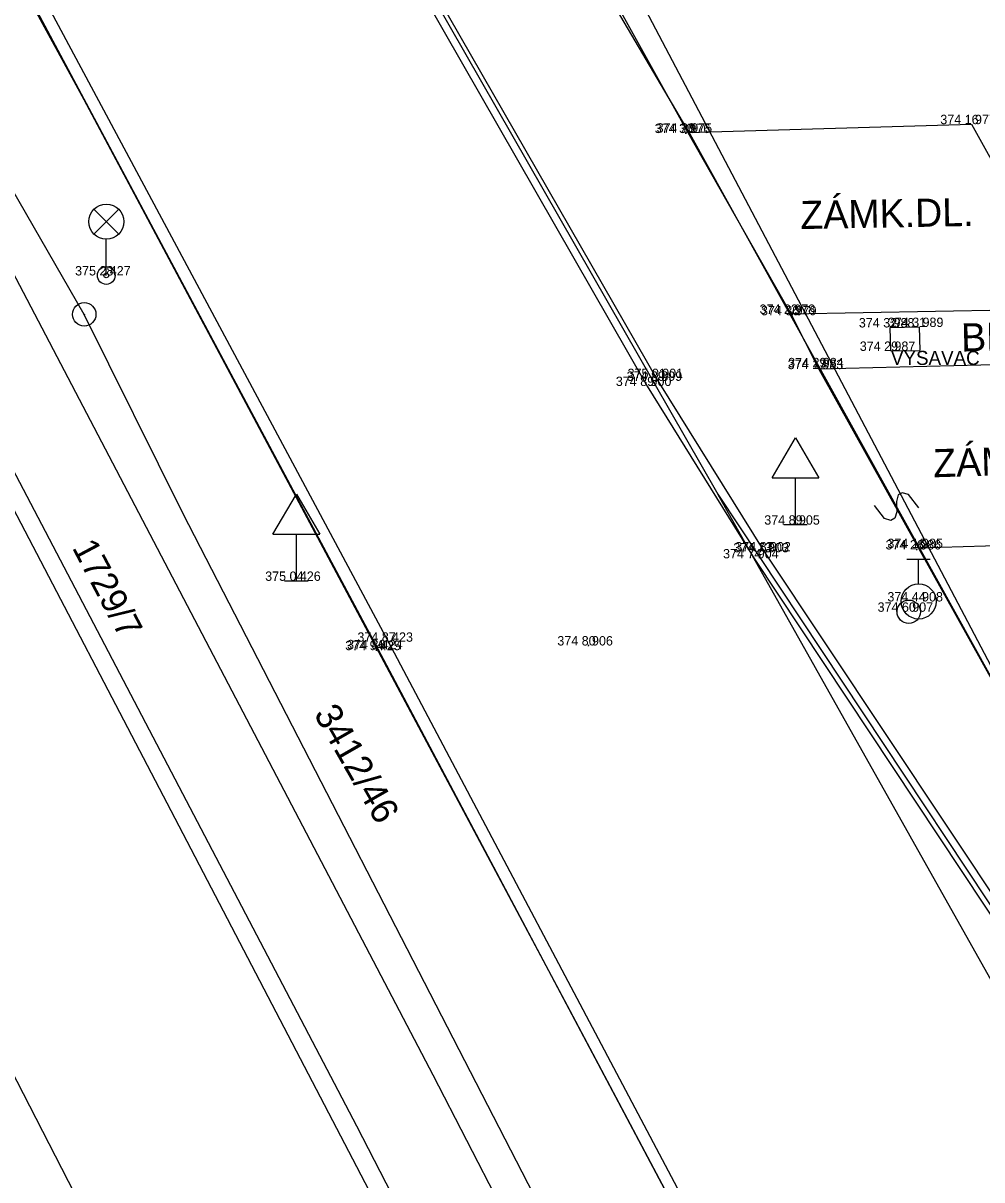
# Model space of a CAD drawing. Extents: x -601196 to -600262, y -1082523 to -1081922.
# Drawn here: x -600574.7 to -600554.22, y -1082148.5 to -1082123.8 of the extents above; entities that cross this region are included whole.
import ezdxf

# ---------------------------------------------------------------- set-up
doc = ezdxf.new("R2010")
doc.units = 0
for name, color, linetype in [('Vrstva 1', 7, 'Continuous'), ('Vrstva 10', 7, 'Continuous'), ('Vrstva 11', 7, 'Continuous'), ('Vrstva 2', 7, 'Continuous'), ('Vrstva 20', 7, 'Continuous'), ('Vrstva 28', 7, 'Continuous'), ('Vrstva 3', 7, 'Continuous'), ('Vrstva 33', 7, 'Continuous'), ('Vrstva 34', 7, 'Continuous'), ('Vrstva 40', 7, 'Continuous'), ('Vrstva 47', 7, 'Continuous'), ('Vrstva 63', 7, 'Continuous')]:
    doc.layers.add(name, color=color, linetype=linetype)

msp = doc.modelspace()

# ---------------------------------------------------------------- linework, layer by layer
at = {"layer": 'Vrstva 1'}
for p, q in [((-600560.54, -1082126.15), (-600560.54, -1082126.15)), ((-600560.5, -1082126.14), (-600560.5, -1082126.14)), ((-600554.44, -1082125.96), (-600554.44, -1082125.96)), ((-600572.92, -1082129.19), (-600572.92, -1082129.19)), ((-600558.3, -1082130.01), (-600558.3, -1082130.01)), ((-600558.27, -1082130.04), (-600558.27, -1082130.04)), ((-600556.18, -1082130.3), (-600556.18, -1082130.3)), ((-600555.56, -1082130.29), (-600555.56, -1082130.29)), ((-600556.16, -1082130.8), (-600556.16, -1082130.8)), ((-600557.7, -1082131.19), (-600557.7, -1082131.19)), ((-600557.69, -1082131.15), (-600557.69, -1082131.15)), ((-600561.37, -1082131.55), (-600561.37, -1082131.55)), ((-600561.14, -1082131.44), (-600561.14, -1082131.44)), ((-600561.12, -1082131.38), (-600561.12, -1082131.38)), ((-600558.2, -1082134.51), (-600558.2, -1082134.51)), ((-600555.61, -1082135.04), (-600555.61, -1082135.04)), ((-600555.57, -1082135.01), (-600555.57, -1082135.01)), ((-600559.08, -1082135.23), (-600559.08, -1082135.23)), ((-600558.86, -1082135.1), (-600558.86, -1082135.1)), ((-600558.82, -1082135.08), (-600558.82, -1082135.08)), ((-600568.86, -1082135.71), (-600568.86, -1082135.71)), ((-600555.57, -1082136.15), (-600555.57, -1082136.15)), ((-600555.78, -1082136.37), (-600555.78, -1082136.37)), ((-600566.89, -1082137.01), (-600566.89, -1082137.01)), ((-600567.15, -1082137.19), (-600567.15, -1082137.19)), ((-600567.11, -1082137.17), (-600567.11, -1082137.17)), ((-600562.62, -1082137.09), (-600562.62, -1082137.09))]:
    msp.add_line(p, q, dxfattribs=at)
at = {"layer": 'Vrstva 10'}
for p, q in [((-600563.37, -1082120.96), (-600560.5, -1082126.14)), ((-600567.11, -1082137.17), (-600575.77, -1082120.97)), ((-600567.06, -1082121.12), (-600561.14, -1082131.44)), ((-600560.5, -1082126.14), (-600558.3, -1082130.01)), ((-600558.3, -1082130.01), (-600552.26, -1082129.9)), ((-600558.3, -1082130.01), (-600557.7, -1082131.19)), ((-600551.63, -1082131.04), (-600557.7, -1082131.19)), ((-600557.7, -1082131.19), (-600555.57, -1082135.01)), ((-600561.14, -1082131.44), (-600558.86, -1082135.1)), ((-600555.57, -1082135.01), (-600551.64, -1082142.08)), ((-600558.86, -1082135.1), (-600551.71, -1082145.85)), ((-600560.36, -1082149.89), (-600567.11, -1082137.17))]:
    msp.add_line(p, q, dxfattribs=at)
at = {"layer": 'Vrstva 11'}
for p, q in [((-600566.89, -1082137.01), (-600575.53, -1082120.88)), ((-600567.27, -1082121.25), (-600561.37, -1082131.55)), ((-600560.5, -1082126.14), (-600554.44, -1082125.96)), ((-600554.44, -1082125.96), (-600552.26, -1082129.9)), ((-600556.18, -1082130.3), (-600555.56, -1082130.29)), ((-600556.16, -1082130.8), (-600556.18, -1082130.3)), ((-600555.56, -1082130.29), (-600555.54, -1082130.79)), ((-600556.16, -1082130.8), (-600555.54, -1082130.79)), ((-600561.37, -1082131.55), (-600559.08, -1082135.23)), ((-600549.55, -1082134.83), (-600555.57, -1082135.01)), ((-600559.08, -1082135.23), (-600551.94, -1082146)), ((-600560.13, -1082149.78), (-600566.89, -1082137.01))]:
    msp.add_line(p, q, dxfattribs=at)
at = {"layer": 'Vrstva 20'}
for p, q in [((-600560.55, -1082126.15), (-600560.53, -1082126.15)), ((-600560.54, -1082126.135), (-600560.54, -1082126.15)), ((-600560.54, -1082126.165), (-600560.54, -1082126.15)), ((-600558.28, -1082130.04), (-600558.26, -1082130.04)), ((-600558.27, -1082130.025), (-600558.27, -1082130.04)), ((-600558.27, -1082130.055), (-600558.27, -1082130.04)), ((-600557.7, -1082131.15), (-600557.68, -1082131.15)), ((-600557.69, -1082131.135), (-600557.69, -1082131.15)), ((-600557.69, -1082131.165), (-600557.69, -1082131.15)), ((-600561.13, -1082131.38), (-600561.11, -1082131.38)), ((-600561.12, -1082131.365), (-600561.12, -1082131.38)), ((-600561.12, -1082131.395), (-600561.12, -1082131.38)), ((-600555.62, -1082135.04), (-600555.6, -1082135.04)), ((-600555.61, -1082135.025), (-600555.61, -1082135.04)), ((-600555.61, -1082135.055), (-600555.61, -1082135.04)), ((-600558.83, -1082135.08), (-600558.81, -1082135.08)), ((-600558.82, -1082135.065), (-600558.82, -1082135.08)), ((-600558.82, -1082135.095), (-600558.82, -1082135.08)), ((-600567.16, -1082137.19), (-600567.14, -1082137.19)), ((-600567.15, -1082137.175), (-600567.15, -1082137.19)), ((-600567.15, -1082137.205), (-600567.15, -1082137.19)), ((-600562.63, -1082137.09), (-600562.61, -1082137.09)), ((-600562.62, -1082137.075), (-600562.62, -1082137.09)), ((-600562.62, -1082137.105), (-600562.62, -1082137.09))]:
    msp.add_line(p, q, dxfattribs=at)
at = {"layer": 'Vrstva 28'}
for p, q in [((-600555.82, -1082135.25), (-600555.32, -1082135.25)), ((-600555.57, -1082135.775), (-600555.57, -1082135.25))]:
    msp.add_line(p, q, dxfattribs=at)
for centre, radius in [((-600555.57, -1082136.15), 0.375), ((-600555.78, -1082136.37), 0.25)]:
    msp.add_circle(centre, radius, dxfattribs=at)
at = {"layer": 'Vrstva 33'}
for p, q in [((-600573.185, -1082127.775), (-600572.655, -1082128.305)), ((-600573.185, -1082128.305), (-600572.655, -1082127.775)), ((-600572.92, -1082129.19), (-600572.92, -1082128.415))]:
    msp.add_line(p, q, dxfattribs=at)
for centre, radius in [((-600572.92, -1082128.04), 0.375), ((-600572.92, -1082129.19), 0.19), ((-600572.92, -1082129.19), 0.05)]:
    msp.add_circle(centre, radius, dxfattribs=at)
at = {"layer": 'Vrstva 34'}
for p, q in [((-600558.7, -1082133.51), (-600558.2, -1082132.66)), ((-600558.2, -1082132.66), (-600557.7, -1082133.51)), ((-600558.7, -1082133.51), (-600557.7, -1082133.51)), ((-600558.2, -1082134.51), (-600558.2, -1082133.51)), ((-600569.36, -1082134.71), (-600568.86, -1082133.86)), ((-600568.86, -1082133.86), (-600568.36, -1082134.71)), ((-600558.45, -1082134.51), (-600557.95, -1082134.51)), ((-600569.36, -1082134.71), (-600568.36, -1082134.71)), ((-600568.86, -1082135.71), (-600568.86, -1082134.71)), ((-600569.11, -1082135.71), (-600568.61, -1082135.71))]:
    msp.add_line(p, q, dxfattribs=at)
at = {"layer": 'Vrstva 47'}
for p, q in [((-600573.39, -1082130.02), (-600587.67, -1082105.3)), ((-600580.35, -1082112.71), (-600573.4, -1082125.43)), ((-600567.34, -1082120.81), (-600559.86, -1082133.86)), ((-600560.45, -1082126.17), (-600563.59, -1082120.83)), ((-600551.63, -1082142.08), (-600562.82, -1082120.81)), ((-600571.36, -1082140.95), (-600580.12, -1082124.2)), ((-600573.4, -1082125.43), (-600563.02, -1082144.88)), ((-600551.63, -1082142.08), (-600560.45, -1082126.17)), ((-600565.94, -1082146.26), (-600576.15, -1082126.77)), ((-600567.57, -1082147.35), (-600577.83, -1082127.77)), ((-600571.28, -1082134.28), (-600573.39, -1082130.02)), ((-600581.31, -1082133.82), (-600565.74, -1082164.04)), ((-600548.05, -1082154.86), (-600559.86, -1082133.86)), ((-600559.86, -1082133.86), (-600541.81, -1082161.08)), ((-600556.005, -1082133.877), (-600556.044, -1082134.013)), ((-600556.044, -1082134.013), (-600556.035, -1082134.236)), ((-600555.918, -1082133.828), (-600556.005, -1082133.877)), ((-600555.782, -1082133.867), (-600555.918, -1082133.828)), ((-600555.568, -1082134.149), (-600555.782, -1082133.867)), ((-600561.65, -1082152.96), (-600571.28, -1082134.28)), ((-600556.297, -1082134.382), (-600556.511, -1082134.1)), ((-600556.035, -1082134.236), (-600556.074, -1082134.372)), ((-600556.161, -1082134.421), (-600556.297, -1082134.382)), ((-600556.074, -1082134.372), (-600556.161, -1082134.421)), ((-600560.4, -1082161.96), (-600571.36, -1082140.95)), ((-600563.02, -1082144.88), (-600549.06, -1082171.12)), ((-600552.31, -1082172.71), (-600565.94, -1082146.26)), ((-600554.01, -1082173.65), (-600567.57, -1082147.35))]:
    msp.add_line(p, q, dxfattribs=at)
for radius in [0.25, 0.005]:
    msp.add_circle((-600573.39, -1082130.02), radius, dxfattribs=at)

# ---------------------------------------------------------------- texts
at = {"layer": 'Vrstva 2'}
for s, p in [(' 977', (-600554.44, -1082125.96)), (' 976', (-600560.54, -1082126.15)), (' 975', (-600560.5, -1082126.14)), (' 427', (-600572.92, -1082129.19)), (' 978', (-600558.3, -1082130.01)), (' 979', (-600558.27, -1082130.04)), (' 988', (-600556.18, -1082130.3)), (' 989', (-600555.56, -1082130.29)), (' 987', (-600556.16, -1082130.8)), (' 983', (-600557.7, -1082131.19)), (' 984', (-600557.69, -1082131.15)), (' 899', (-600561.14, -1082131.44)), (' 901', (-600561.12, -1082131.38)), (' 900', (-600561.37, -1082131.55)), (' 905', (-600558.2, -1082134.51)), (' 904', (-600559.08, -1082135.23)), (' 903', (-600558.86, -1082135.1)), (' 902', (-600558.82, -1082135.08)), (' 986', (-600555.61, -1082135.04)), (' 985', (-600555.57, -1082135.01)), (' 426', (-600568.86, -1082135.71)), (' 908', (-600555.57, -1082136.15)), (' 907', (-600555.78, -1082136.37)), (' 425', (-600567.15, -1082137.19)), (' 424', (-600567.11, -1082137.17)), (' 423', (-600566.89, -1082137.01)), (' 906', (-600562.62, -1082137.09))]:
    msp.add_text(s, height=0.2, dxfattribs=at).set_placement(p)
at = {"layer": 'Vrstva 3'}
for s, p in [('374 16 ', (-600555.106, -1082125.96)), ('374 30 ', (-600561.206, -1082126.15)), ('374 20 ', (-600561.166, -1082126.14)), ('375 28 ', (-600573.586, -1082129.19)), ('374 22 ', (-600558.966, -1082130.01)), ('374 30 ', (-600558.936, -1082130.04)), ('374 32 ', (-600556.846, -1082130.3)), ('374 31 ', (-600556.226, -1082130.29)), ('374 29 ', (-600556.826, -1082130.8)), ('374 17 ', (-600558.366, -1082131.19)), ('374 29 ', (-600558.356, -1082131.15)), ('374 89 ', (-600561.806, -1082131.44)), ('375 01 ', (-600561.786, -1082131.38)), ('374 89 ', (-600562.036, -1082131.55)), ('374 89 ', (-600558.866, -1082134.51)), ('374 74 ', (-600559.746, -1082135.23)), ('374 73 ', (-600559.526, -1082135.1)), ('374 87 ', (-600559.486, -1082135.08)), ('374 26 ', (-600556.276, -1082135.04)), ('374 16 ', (-600556.236, -1082135.01)), ('375 04 ', (-600569.526, -1082135.71)), ('374 44 ', (-600556.236, -1082136.15)), ('374 60 ', (-600556.446, -1082136.37)), ('374 94 ', (-600567.816, -1082137.19)), ('374 86 ', (-600567.776, -1082137.17)), ('374 87 ', (-600567.556, -1082137.01)), ('374 80 ', (-600563.286, -1082137.09))]:
    msp.add_text(s, height=0.2, dxfattribs=at).set_placement(p)
at = {"layer": 'Vrstva 40'}
for s, rotation, p in [('ZÁMK.DL.', 1.0434, (-600558.091, -1082128.2)), ('BET.', 1.4156, (-600554.655, -1082130.816)), ('ZÁMK.DL.', 1.7127, (-600555.249, -1082133.5))]:
    msp.add_text(s, height=0.6, rotation=rotation, dxfattribs=at).set_placement(p)
at = {"layer": 'Vrstva 47'}
for s, height, rotation, p in [('1729/7', 0.55, 297.9, (-600573.66, -1082135)), ('3412/46', 0.57, 299.817, (-600568.499, -1082138.552))]:
    msp.add_text(s, height=height, rotation=rotation, dxfattribs=at).set_placement(p)
at = {"layer": 'Vrstva 63'}
msp.add_text('VYSAVAC', height=0.3, dxfattribs=at).set_placement((-600556.16, -1082131.1))

doc.saveas('drawing.dxf')
